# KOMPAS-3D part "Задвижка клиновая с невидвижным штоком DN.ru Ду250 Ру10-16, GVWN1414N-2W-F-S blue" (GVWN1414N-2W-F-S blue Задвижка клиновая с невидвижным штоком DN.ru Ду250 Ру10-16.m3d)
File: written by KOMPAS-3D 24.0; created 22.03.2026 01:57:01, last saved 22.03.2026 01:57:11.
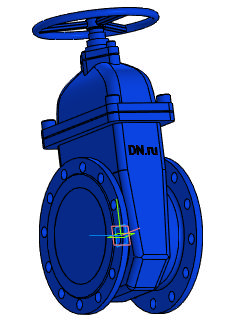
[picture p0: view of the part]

Document properties: Автор: R2D2; Полное имя файла: E:\Работа\Зайцев\GVWN1414N-2W-F-S blue Задвижка клиновая с невидвижным штоком DN.ru Ду40-300 Ру10-16\DN250\GVWN1414N-2W-F-S blue Задвижка клиновая с невидвижным штоком DN.ru Ду250 Ру10-16.m3d

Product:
- Part/product: Задвижка клиновая с невидвижным штоком DN.ru Ду250 Ру10-16  | designation GVWN1414N-2W-F-S blue
    Масса: 75
    Раздел спецификации: Прочие изделия
    Примечание: D040-10586

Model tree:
1. Операция без истории:1
2. Скругление:1  (with: Ребро.Операция без истории:1)
     Радиус = 10

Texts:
  GVWN1414N-2W-F-S blue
